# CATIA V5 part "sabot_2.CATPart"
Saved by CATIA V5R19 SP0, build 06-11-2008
Part number: skl_sabot_2
Publications: "axe_pivot_sabot2_bielette3", "axe_pivot_sabot2_batit", "Plan.1", "lineaire_rect_sabot2_roue2", "Point.2"
Bounding box of the stored display mesh (mm): x -240 to -110, y 330 to 560, z -20 to 20
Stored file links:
  C:\Users\Thibaud\Desktop\IFMA\thinkmotion\IAO\modele_catia\squelette\sabot_2.CATPart
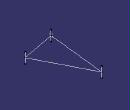
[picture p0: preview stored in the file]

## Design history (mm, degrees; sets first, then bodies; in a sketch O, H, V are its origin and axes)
Body1 (main body)
  Point1: stored without definition
  Point2: stored without definition
  Line1: type PtPt, SecondPoint Point2, FirstPoint Point1
  Point3: stored without definition
  Point4: stored without definition
  Line2: type PtPt, SecondPoint Point4, FirstPoint Point3
  Point5: stored without definition
  Point6: stored without definition
  Line3: type PtPt, SecondPoint Point6, FirstPoint Point5
  Plane1: stored without definition
  Point7: stored without definition
  Line4 "lineaire_rect_sabot2_roue2": type Normal, RefSkin Plane1, Start -20, End 20, RefPoint Point7
  Plane2: stored without definition
  Point8: stored without definition
  Line5 "axe_pivot_sabot2_batit": type Normal, RefSkin Plane2, Start -20, End 20, RefPoint Point8
  Plane3: stored without definition
  Point9: stored without definition
  Line6 "axe_pivot_sabot2_bielette3": type Normal, RefSkin Plane3, Start -20, End 20, RefPoint Point9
